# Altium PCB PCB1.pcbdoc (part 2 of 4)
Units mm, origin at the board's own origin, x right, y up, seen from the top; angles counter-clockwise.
Board outline 77.9 x 109.02 mm, 4 copper layers (Top Layer, Inner1, Inner2, Bottom Layer); 129 components, 135 nets, 715 pads, 425 vias.
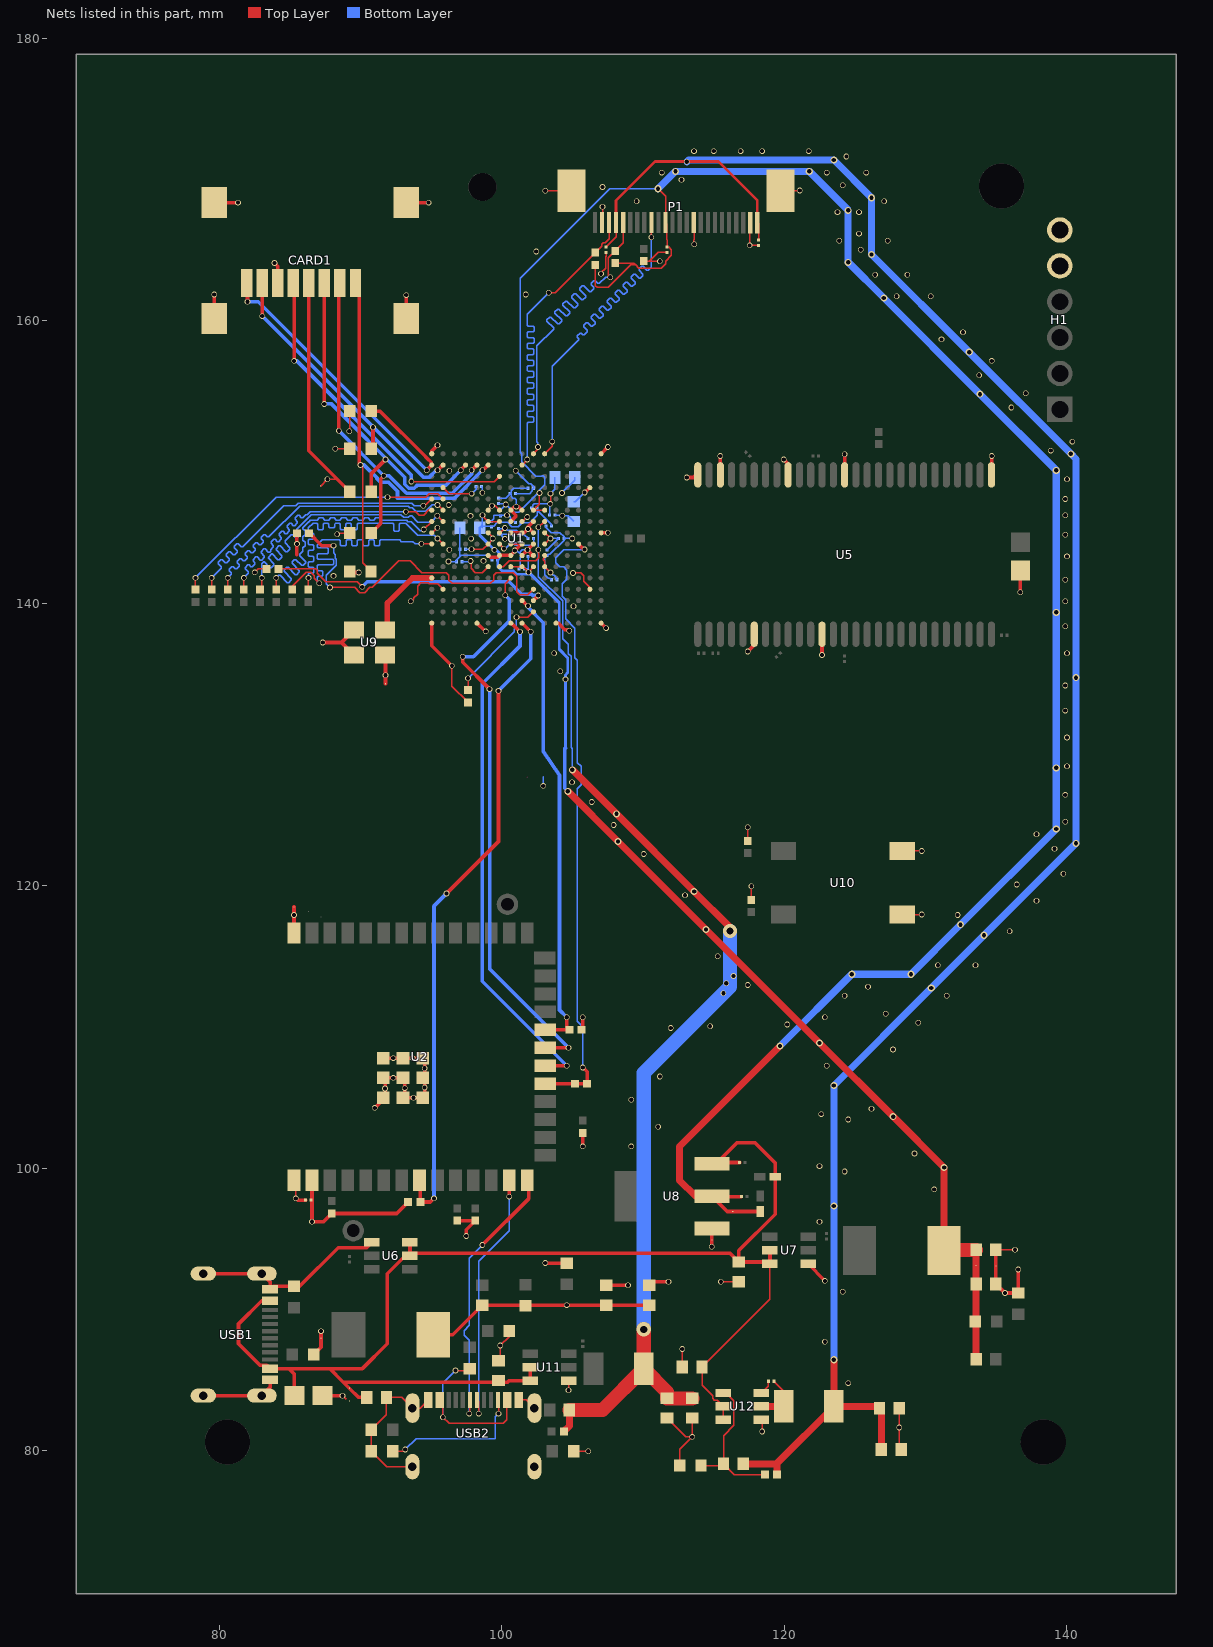
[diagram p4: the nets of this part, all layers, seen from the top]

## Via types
v1: diameter 0.4, hole 0.3, Top Layer to Bottom Layer, 387 vias
v2: diameter 0.5, hole 0.3, Top Layer to Bottom Layer, 36 vias
v3: diameter 1, hole 0.5, Top Layer to Bottom Layer, 2 vias

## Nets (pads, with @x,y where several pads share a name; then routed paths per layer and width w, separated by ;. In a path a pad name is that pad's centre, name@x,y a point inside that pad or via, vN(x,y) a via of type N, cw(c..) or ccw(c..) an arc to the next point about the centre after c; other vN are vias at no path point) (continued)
$1N63772: R42.1 USB2.B5 | length 10.5
  Top Layer w0.1: R42.1@92.252,79.942 93.023,79.942 v1(93.15,80.069) ; USB2.B5@99.726,83.574 99.754,83.546 v1(99.754,82.609)
  Bottom Layer w0.1: v1(93.15,80.069) 93.912,80.831 99.5,80.831 99.528,80.859 99.528,82.383 v1(99.754,82.609)
$1N63825: R44.2 USB2.A4B9 USB2.B4A9 | length 12.3
  Top Layer w0.1: USB2.A4B9@95.576,83.574 95.817,83.333 v1(95.817,82.355) 96.256,81.915 100.076,81.915 100.339,82.178 100.339,83.537 USB2.B4A9@100.376,83.574 ; v1(96.706,85.657) 97.586,85.657 R44.2@97.722,85.792
  Bottom Layer w0.1: v1(95.817,82.355) 95.817,84.768 v1(96.706,85.657)
$1N64401: C69.2 L4.1 U12.5 | length 3.6
  Top Layer w0.1: C69.2@119.253,84.895 119.95,84.198 L4.1@119.95,83.117
  Top Layer w0.5: U12.5@118.376,83.117 L4.1@119.95,83.117
$1N64402: C69.1 U12.6 | length 1
  Top Layer w0.1: U12.6@118.376,84.067 118.863,84.554 C69.1@118.863,84.895
$1N64403: C70.1 R46.2 R47.1 U12.1 | length 10.6
  Top Layer w0.1: R46.2@114.096,78.926 115.564,78.926 C70.1@115.691,79.053 ; U12.1@115.676,84.067 115.737,84.006 115.922,84.006 116.428,83.5 116.428,81.783 115.691,81.046 C70.1@115.691,79.053 ; R47.1@118.625,78.291 116.453,78.291 C70.1@115.691,79.053
$2N5507: R23.2 U1.P10 | length 20
  Top Layer w0.1: R23.2@84.185,142.426 86.8,142.426 86.906,142.32 86.906,142.132 87.522,141.516 89.742,141.516 v1(90.102,141.156)
  Top Layer w0.254: U1.P10@102.224,140.185 102.548,140.509 v1@102.548,140.521
  Bottom Layer w0.254: v1(90.102,141.156) 90.46,141.514 100.509,141.514 101.38,140.642 102.088,140.642 102.188,140.542 v1@102.569,140.542
  other v1: 102.569,140.542
$2N5509: R24.2 U1.N10 | length 23.9
  Top Layer w0.1: v1(87.816,141.114) 89.575,141.114 89.935,140.754 90.268,140.754 90.628,141.114 90.822,141.114 92.066,142.358 92.066,142.363 92.702,142.999 93.495,142.999 94.327,142.167 96.038,142.167 96.242,141.962 96.242,141.626 96.466,141.403 98.382,141.403 98.389,141.41 98.858,141.41 98.866,141.403 99.182,141.403 99.406,141.626 99.406,141.985 99.588,142.167 100.782,142.167 101.042,141.907 101.042,140.827 101.266,140.603 101.842,140.603 U1.N10@102.224,140.985
  Top Layer w0.254: R24.2@86.344,144.966 87.233,144.077 v1(88.07,144.077)
  Bottom Layer w0.1: v1(87.816,141.114) 87.562,141.368 87.562,141.992 88.27,142.7 88.27,143.125 88.197,143.198 88.197,143.442 88.07,143.569 v1(88.07,144.077)
$2N5511: R25.2 U1.R10 | length 7.9
  Top Layer w0.1: R25.2@97.595,133.842 v1(97.595,134.679) ; v1(101.024,138.997) 101.836,138.997 U1.R10@102.224,139.385
  Bottom Layer w0.1: v1(97.595,134.679) 100.876,137.96 100.876,138.147 101.024,138.295 v1(101.024,138.997)
+1V1: C25.2 C27.2 C28.2 C41.1 C42.1 C43.1 C44.1 C49.1 C53.1 C54.1 C61.1 L2.2 pad.55@104.453,129.091 pad.55@133.577,93.091 R15.2 U1.G6 U1.G7 U1.L8 U1.L9 U1.L10 | length 88.4
  Top Layer w0.1: v1@98.611,146.236 98.611,146.198 U1.G6@99.024,145.785 U1.G7@99.824,145.785 ; U1.L8@100.624,142.585 U1.L9@101.424,142.585 101.49,142.585 v1(101.882,142.193) 102.224,142.534 U1.L10@102.224,142.585
  Top Layer w0.5: v2(104.663,126.678) v2(108.218,123.123) v2(114.455,116.886) v2(122.493,108.847) v2(127.705,103.636) v2(131.313,100.028) L2.2@131.313,94.16 ; C25.2@133.577,86.458 C28.2@133.577,91.792 pad.55@133.577,93.091 C27.2@133.577,94.205
  Top Layer w1: L2.2@131.313,94.16 131.357,94.205 C27.2@133.577,94.205
  Bottom Layer w0.1: C61.1@98.485,145.41 98.619,145.544 v1(98.619,146.228) ; C61.1@98.549,145.347 98.652,145.45 99.401,145.45 99.673,145.723 100.394,145.723 100.701,145.416 101.145,145.416 101.434,145.707 101.952,145.707 102.489,146.243 102.489,146.49 ; C53.1@101.6,142.426 101.786,142.426 101.854,142.358 C49.1@101.854,143.315 ; C43.1@102.489,146.744 102.489,146.49 ; C44.1@103.505,145.474 103.505,145.584 102.599,146.49 102.489,146.49
  Bottom Layer w0.2: C61.1@98.422,145.347 98.422,144.814 v1(99.461,143.774) 99.589,143.774 99.683,143.68 99.683,143.677 99.789,143.571 99.789,143.155 C54.1@99.695,143.061 99.695,142.612 100.008,142.299 100.765,142.299 101.019,142.045 101.869,142.045 v1@101.882,142.058 ; v1(101.882,142.193) 101.892,142.193 104.052,140.033 104.052,137.287 104.06,137.279 104.06,136.905 104.052,136.897 104.052,136.735 104.651,136.136 104.651,135.071 104.499,134.919 v1(104.499,134.604) 104.499,129.729
  Bottom Layer w0.254: 104.499,129.729 104.453,129.729 pad.55@104.453,129.091 104.453,126.888 v2(104.663,126.678)
+1V8: C29.1 C32.2 C35.1 C62.1 C63.1 P1.11 pad.55@116.341,96.923 R38.2 R39.2 U1.F10 U1.F11 U8.2 | length 162.2
  Top Layer w0.1: v1(102.656,147.8) 102.656,147.557 102.642,147.543 102.642,147.227 102.656,147.212 102.656,147.017 U1.F10@102.224,146.585 U1.F11@103.024,146.585 ; R38.2@106.612,163.964 106.612,163.501 106.608,163.497 106.608,162.495 106.739,162.365 107.521,162.365 109.12,163.964 109.456,163.964 ; R39.2@108.009,164.091 109.329,164.091 109.456,163.964 ; v2(111.057,169.35) 111.581,168.825 P1.11@111.581,166.951 111.679,166.853 111.679,165.754 111.692,165.742 C35.1@111.692,165.227 ; 111.802,165.227 112.004,165.025 112.004,164.648 111.586,164.23 111.586,164.051 111.267,163.733 109.687,163.733 109.456,163.964
  Top Layer w0.254: C29.1@116.958,97.976 114.889,97.976 115.943,96.923 pad.55@116.341,96.923 C32.2@118.296,96.923
  Top Layer w0.5: U8.2@114.861,98.005 113.695,98.005 112.581,99.119 112.581,101.532 v2(119.693,108.644)
  Bottom Layer w0.1: C63.1@99.754,147.057 100.2,147.057 v1(100.271,146.985) ; C62.1@99.881,146.558 99.881,146.594 v1(100.271,146.985) ; v2(111.057,169.35) 107.628,169.35 101.278,163 101.278,150.681 101.384,150.575 101.384,150.006 102.396,148.994 102.827,148.994 102.863,149.03 102.929,149.03 103.044,148.915 103.044,148.388 102.656,148.001 v1(102.656,147.8) 102.544,147.8 101.181,146.437 100.848,146.437 100.3,146.985 v1(100.271,146.985)
  Bottom Layer w0.5: v2(111.057,169.35) v2(112.294,170.587) v2(121.758,170.587) v2(124.519,167.826) v2(124.519,164.143) v2(127.042,161.62) v2(133.861,154.801) v2(139.251,149.411) v2(139.251,139.352) v2(139.251,128.338) v2(139.251,124.011) v2(132.473,117.233) v2(128.964,113.724) v2(124.773,113.724) v2(119.693,108.644)
+2V5: C65.2 C67.2 C68.2 L3.2 R41.2 U1.G11 U1.L7 | length 84.7
  Top Layer w0.1: U1.L7@99.824,142.585 100.084,142.585 100.502,143.003 102.382,143.003 102.606,143.227 102.606,143.543 102.576,143.573 v1(102.576,143.785) ; v1(102.576,145.385) 102.976,145.785 U1.G11@103.024,145.785
  Top Layer w0.5: R41.2@104.378,81.339 104.772,81.733 C65.2@104.772,82.863 ; v2(104.982,128.202) v2(108.1,125.084) v2(113.609,119.574) 116.137,117.047 v3(116.137,116.772)
  Top Layer w1: C65.2@104.772,82.863 107.117,82.863 L3.2@110.038,85.784 ; v3(110.038,88.578) L3.2@110.038,85.784 ; C67.2@113.47,83.69 C68.2@111.692,83.69 111.692,84.13 L3.2@110.038,85.784
  Bottom Layer w0.1: v1(102.576,145.385) v1(102.576,143.785) 102.576,141.889 104.302,140.164 104.302,137.497 104.707,137.092 104.707,136.434 104.901,136.24 104.901,129.786 104.982,129.705 v2(104.982,128.202)
  Bottom Layer w1: v3(110.038,88.578) 110.038,106.736 v1(115.679,112.377) 116.137,112.835 v3(116.137,116.772)
  other v1: 115.883,113.089 116.391,113.597
+2V8: C34.1 C70.2 C72.2 C73.2 C74.1 L4.2 P1.4 P1.24 R47.2 | length 146.6
  Top Layer w0.1: C34.1@107.374,165.227 108.081,165.934 P1.4@108.081,166.951 ; P1.24@118.083,166.948 118.169,166.862 C74.1@118.169,165.735
  Top Layer w0.2: P1.4@108.081,166.951 108.081,168.526 110.831,171.276 115.33,171.276 118.083,168.523 P1.24@118.083,166.948
  Top Layer w0.5: C70.2@117.091,79.053 119.436,79.053 ; R47.2@119.491,78.291 119.491,78.998 119.436,79.053 ; L4.2@123.503,83.12 v2(123.503,86.419) ; C73.2@126.74,82.99 126.613,83.117 L4.2@123.5,83.117 119.436,79.053 ; C72.2@126.867,80.069 C73.2@126.867,82.863
  Bottom Layer w0.5: v1(113.089,171.255) 113.216,171.382 v2(123.503,171.382) v2(126.17,168.715) v2(126.17,164.695) v2(133.091,157.775) v2(140.284,150.581) 140.648,150.217 v2(140.648,134.724) v2(140.648,122.995) v2(134.135,116.482) v2(130.4,112.747) v2(123.503,105.85) v2(123.503,97.303) v2(123.503,86.419)
+3V3: C8.2 C17.2 C19.2 C22.2 C23.2 C37.1 C39.1 C40.1 C45.1 C46.1 C47.1 C48.1 C50.1 C51.1 C52.1 C55.1 C56.1 C57.1 C58.1 C59.1 CARD1.4 H1.5 L1.2 pad.55@87.15,148.289 R3.1 R4.1 R5.2 R7.2 R11.2 R16.2 R17.2 R18.2 R19.2 R20.2 R21.2 R22.2 R23.1 U1.F6 U1.F7 U1.G9 U1.H6 U1.H7 U1.H11 U1.J6 U1.J7 U1.J11 U1.K11 U1.L6 U1.L11 U2.2 U9.1 U9.4 | length 81.8
  Top Layer w0.1: v1(82.484,142.183) 82.727,142.426 R23.1@83.319,142.426 ; pad.55@87.15,148.289 v1(87.637,148.776) 88.328,148.776 88.33,148.778 ; v1(88.197,150.935) R18.2@89.221,150.935 ; v1(88.324,144.881) 88.409,144.966 R17.2@89.221,144.966 ; v1@89.221,152.205 R19.2@89.221,153.602 ; v1(97.776,142.985) 97.806,142.955 97.806,142.462 98.096,142.172 98.611,142.172 U1.L6@99.024,142.585 ; v1@97.849,143.823 98.045,143.823 98.065,143.803 98.642,143.803 U1.J6@99.024,144.185 99.352,144.513 v1(99.352,144.584) 99.352,144.657 U1.H6@99.024,144.985 ; U1.F6@99.024,146.585 99.292,146.853 v1(99.292,146.902) 99.506,146.902 U1.F7@99.824,146.585 ; U1.J7@99.824,144.185 100.135,143.874 v1@100.135,143.823 ; U1.H7@99.824,144.985 99.871,144.985 v1(100.207,145.321) ; U1.G9@101.424,145.785 101.748,146.109 v1(101.786,146.109) ; U1.K11@103.024,143.385 103.024,143.258 102.929,143.163 102.929,143.061 103.024,142.966 U1.L11@103.024,142.585 v1(103.437,142.172) ; U1.J11@103.024,144.185 103.424,144.585 v1(103.437,144.585) 103.037,144.985 U1.H11@103.024,144.985
  Top Layer w0.254: CARD1.4@86.319,162.67 86.319,150.789 88.33,148.778 R20.2@89.221,147.887 ; U2.2@86.668,99.132 86.546,99.01 v1(86.546,96.198) 87.36,96.198 R7.2@87.943,96.781 92.538,96.781 R5.2@93.352,97.595 ; v1(87.308,137.219) 88.635,137.219 ; R16.2@89.217,142.247 89.293,142.172 v1(89.848,142.172) ; U9.1@89.51,136.344 88.635,137.219 ; U9.4@89.51,138.094 88.635,137.219 ; L1.2@95.134,88.197 96.517,88.197 C19.2@98.611,90.291 101.605,90.291 R11.2@101.659,90.237 101.712,90.291 v1(104.594,90.291) C23.2@107.374,90.291 C22.2@110.422,90.291 ; R21.2@96.833,96.273 R22.2@98.103,96.273 97.468,95.638 v1(97.468,95.182) ; R3.1@105.648,109.787 105.723,109.862 v1(105.723,110.676) ; v1(105.723,101.532) R4.1@105.723,102.496 ; v1(136.711,140.775) C8.2@136.711,142.315
  Bottom Layer w0.1: C51.1@97.155,142.934 97.725,142.934 v1(97.776,142.985) ; C56.1@97.409,143.823 97.833,143.823 v1(97.841,143.815) ; C37.1@98.552,148.268 98.611,148.209 v1(98.611,147.819) ; C45.1@99.754,145.288 100.174,145.288 v1(100.207,145.321) 100.377,145.151 101.017,145.151 101.136,145.032 101.136,144.922 C46.1@101.219,144.839 101.591,144.839 C47.1@101.845,144.585 ; v1(100.135,143.864) 100.235,143.864 C57.1@100.575,144.204 ; C50.1@100.965,147.76 101.964,147.76 102.152,147.947 102.152,148.058 C39.1@102.235,148.141 102.235,148.251 102.033,148.453 101.908,148.453 v1(100.976,149.385) ; C52.1@103.183,143.764 C55.1@104.004,144.585 v1(103.437,144.585) ; v1(103.437,142.172) 103.633,141.976 103.684,141.976 103.886,141.774 C48.1@103.886,141.664 ; C40.1@103.759,146.236 104.22,146.236 v1(104.27,146.186) 104.692,146.186 C59.1@105.088,145.79 ; v1(104.248,147.808) 105.153,148.712 C58.1@105.153,148.903
  other v1: 88.07,141.932 89.188,152.171
+5V: C20.2 C26.2 C30.1 C31.2 C33.2 C66.2 C71.2 pad.55@89.194,84.406 U6.2 U6.3 U7.2 U7.3 U8.3 U11.2 U11.3 U12.2 U12.3 USB1.A4B9 USB1.B4A9 | length 100.1
  Top Layer w0.1: U12.3@115.676,82.167 U12.2@115.676,83.117 115.228,83.565 115.042,83.565 114.924,83.683 114.924,83.869 114.17,84.623 C71.2@114.17,85.911 118.978,90.719 U7.3@118.978,93.216
  Top Layer w0.254: USB1.A4B9@83.574,90.597 82.977,90.597 81.339,88.959 81.339,87.563 82.884,86.018 83.353,86.018 USB1.B4A9@83.574,85.797 84.904,85.797 ; C33.2@85.292,83.879 85.292,85.409 84.904,85.797 ; C20.2@90.418,83.752 89.848,83.752 pad.55@89.194,84.406 88.767,84.833 ; U6.3@93.484,94.735 U6.2@93.484,93.785 ; U11.2@102.013,85.883 U11.3@102.013,84.933 100.489,84.933 100.389,84.833 88.767,84.833 ; U8.3@114.861,100.305 115.164,100.305 U8.3@115.248,100.389 ; C30.1@116.831,100.389 U8.3@115.248,100.389 ; U7.2@118.978,94.166 U7.3@118.978,93.216 118.852,93.342 C26.2@116.772,93.342 ; 84.904,85.797 87.803,85.797 ; 87.803,85.797 90.115,85.797 91.88,87.562 91.88,92.515 93.15,93.785 U6.2@93.484,93.785 ; 87.803,85.797 88.767,84.833 ; U6.2@93.484,93.785 93.649,93.95 116.163,93.95 C26.2@116.772,93.342 ; U8.3@115.248,100.389 116.645,101.786 117.915,101.786 119.349,100.352 C31.2@119.349,99.373 119.349,96.731 116.772,94.154 C26.2@116.772,93.342
CCLK: R6.1 R6.2 U1.J14 U2.19 | length 44.6
  Top Layer w0.254: U2.19@103.188,105.977 R6.1@105.163,105.977 R6.2@106.029,105.977 106.029,106.814 v1(105.723,107.12) ; U1.J14@105.424,144.185 105.807,143.802 v1(105.85,143.802)
  Bottom Layer w0.1: v1(105.723,107.12) 105.723,109.998 105.321,110.4 105.321,126.873 105.596,127.148 105.596,128.456 105.342,128.71 105.321,128.71 105.321,135.97 105.169,136.122 105.169,138.224 104.51,138.882 104.51,140.247 104.282,140.475 104.282,141.366 104.601,141.685 104.601,142.338 104.365,142.574 104.08,142.574 103.795,142.858 103.795,143.226 104.371,143.802 v1(105.85,143.802)
CRYSTAL: U1.M1 U9.3 | length 5.9
  Top Layer w0.4: U9.3@91.71,138.094 91.88,138.264 91.88,140.013 93.652,141.785 U1.M1@95.024,141.785
D0: R26.1 U1.E2 | length 21
  Top Layer w0.1: R26.1@78.291,140.954 v1(78.291,141.791) ; v1@91.88,147.506 94.604,147.506 94.866,147.767 95.442,147.767 U1.E2@95.824,147.385
  Bottom Layer w0.1: v1(78.291,141.791) 84.006,147.506 v1(91.889,147.506)
D1: R27.1 U1.E1 | length 21.1
  Top Layer w0.1: R27.1@79.434,140.954 v1(79.434,141.791) ; v1(94.42,146.9) 94.539,146.9 U1.E1@95.024,147.385
  Bottom Layer w0.1: v1(79.434,141.791) 80.119,142.476 80.119,142.576 79.901,142.793 79.901,142.893 80.084,143.076 80.184,143.076 80.402,142.859 80.502,142.859 80.685,143.042 80.685,143.142 80.467,143.359 80.467,143.459 80.65,143.642 80.75,143.642 80.967,143.424 81.067,143.424 81.25,143.607 81.25,143.707 81.033,143.925 81.033,144.025 81.216,144.208 81.316,144.208 81.533,143.99 81.633,143.99 84.543,146.9 85.403,146.9 85.581,147.078 93.613,147.078 93.791,146.9 v1(94.42,146.9)
D2: R28.1 U1.F2 | length 21.5
  Top Layer w0.1: R28.1@80.577,140.954 v1(80.577,141.791) ; v1(95.433,146.955) 95.454,146.955 U1.F2@95.824,146.585
  Bottom Layer w0.1: v1(80.577,141.791) 80.831,142.045 80.831,142.145 80.677,142.299 80.677,142.399 80.86,142.582 80.96,142.582 81.114,142.428 81.214,142.428 81.396,142.61 81.396,142.71 81.242,142.864 81.242,142.964 81.425,143.147 81.525,143.147 81.679,142.993 81.779,142.993 81.962,143.176 81.962,143.276 81.808,143.43 81.808,143.53 81.991,143.713 82.091,143.713 82.245,143.559 82.345,143.559 82.528,143.742 82.528,143.842 82.374,143.996 82.374,144.096 82.557,144.279 82.657,144.279 82.811,144.125 82.911,144.125 83.094,144.308 83.094,144.408 82.94,144.562 82.94,144.662 83.122,144.844 83.222,144.844 83.376,144.69 83.476,144.69 85.664,146.878 93.361,146.878 93.471,146.768 93.639,146.768 93.91,146.498 94.586,146.498 95.043,146.955 v1(95.433,146.955)
D3: R29.1 U1.F1 | length 20.7
  Top Layer w0.1: R29.1@81.72,140.954 v1(81.72,141.791) ; v1(93.195,146.476) 93.894,146.476 94.126,146.244 94.459,146.244 94.817,146.602 95.007,146.602 U1.F1@95.024,146.585
  Bottom Layer w0.1: v1(81.72,141.791) 82.039,142.11 82.039,142.21 81.822,142.428 81.822,142.528 82.004,142.71 82.104,142.71 82.224,142.591 82.324,142.591 82.507,142.774 82.507,142.874 82.387,142.993 82.387,143.093 82.57,143.276 82.67,143.276 82.888,143.059 82.988,143.059 83.17,143.241 83.17,143.341 82.953,143.559 82.953,143.659 83.136,143.842 83.236,143.842 83.453,143.624 83.553,143.624 83.606,143.677 83.606,143.773 83.818,143.985 83.818,144.085 83.649,144.255 83.649,144.355 83.831,144.537 83.931,144.537 84.101,144.368 84.201,144.368 84.384,144.551 84.384,144.651 84.214,144.82 84.214,144.92 84.397,145.103 84.497,145.103 84.666,144.934 84.766,144.934 84.949,145.117 84.949,145.217 84.78,145.386 84.78,145.486 84.963,145.669 85.063,145.669 85.232,145.5 85.332,145.5 85.515,145.682 85.515,145.782 85.346,145.952 85.346,146.052 85.529,146.235 85.629,146.235 85.798,146.065 85.898,146.065 86.106,146.274 86.203,146.274 86.405,146.476 v1(93.195,146.476)
D4: R30.1 U1.G2 | length 21.3
  Top Layer w0.1: R30.1@82.863,140.954 82.99,141.081 v1(82.99,141.791) ; v1(95.418,146.188) 95.421,146.188 U1.G2@95.824,145.785
  Bottom Layer w0.1: v1(82.99,141.791) 82.99,142.778 83.136,142.924 83.154,142.924 83.566,142.512 83.666,142.512 83.849,142.695 83.849,142.795 83.437,143.207 83.437,143.225 83.702,143.49 83.72,143.49 84.132,143.078 84.232,143.078 84.414,143.261 84.414,143.361 84.003,143.773 84.003,143.873 84.185,144.056 84.285,144.056 84.697,143.644 84.797,143.644 84.98,143.827 84.98,143.927 84.641,144.266 84.641,144.429 85.066,144.855 85.166,144.855 85.385,144.636 85.485,144.636 85.668,144.819 85.668,144.919 85.449,145.137 85.449,145.237 86.488,146.276 92.826,146.276 93.028,146.074 93.361,146.074 93.488,146.201 93.597,146.201 94.049,145.749 94.978,145.749 v1(95.418,146.188)
D5: R31.1 U1.G1 | length 21
  Top Layer w0.1: R31.1@84.006,140.954 v1(84.006,141.791) ; v1(94.453,145.22) 94.459,145.22 U1.G1@95.024,145.785
  Bottom Layer w0.1: v1(84.006,141.791) 84.185,141.97 84.285,141.97 84.794,141.461 84.894,141.461 85.077,141.643 85.077,141.743 84.567,142.252 84.567,142.352 84.75,142.535 84.85,142.535 85.359,142.026 85.459,142.026 85.642,142.209 85.642,142.309 85.133,142.818 85.133,142.918 85.297,143.082 85.397,143.082 85.809,142.669 85.909,142.669 86.092,142.852 86.092,142.952 85.68,143.365 85.68,143.465 85.88,143.665 85.88,143.923 85.951,143.993 85.992,143.993 86.063,144.064 86.063,144.323 85.992,144.393 85.951,144.393 85.88,144.464 85.88,144.723 85.951,144.793 85.992,144.793 86.063,144.864 86.063,145.123 85.992,145.193 85.951,145.193 85.88,145.264 85.88,145.337 86.326,145.784 86.348,145.784 86.438,145.874 86.923,145.874 86.994,145.945 86.994,145.976 87.065,146.047 87.323,146.047 87.394,145.976 87.394,145.945 87.465,145.874 87.723,145.874 87.794,145.945 87.794,145.976 87.865,146.047 88.123,146.047 88.194,145.976 88.194,145.945 88.265,145.874 88.523,145.874 88.594,145.945 88.594,145.976 88.665,146.047 88.923,146.047 88.994,145.976 88.994,145.945 89.065,145.874 89.323,145.874 89.394,145.945 89.394,145.976 89.465,146.047 89.723,146.047 89.794,145.976 89.794,145.945 89.865,145.874 90.123,145.874 90.194,145.945 90.194,145.976 90.265,146.047 90.523,146.047 90.594,145.976 90.594,145.945 90.665,145.874 90.923,145.874 90.994,145.945 90.994,145.976 91.065,146.047 91.323,146.047 91.394,145.976 91.394,145.945 91.465,145.874 93.249,145.874 93.339,145.784 93.568,145.784 94.222,145.13 94.363,145.13 v1(94.453,145.22)
D6: R32.1 U1.J1 | length 20.9
  Top Layer w0.1: R32.1@85.149,140.954 85.149,141.216 86.125,142.193 86.458,142.193 86.694,141.957 86.694,141.77 v1(87.054,141.41) ; v1(94.293,144.204) 95.005,144.204 U1.J1@95.024,144.185
  Bottom Layer w0.1: v1(87.054,141.41) 86.906,141.558 86.906,141.842 86.977,141.913 87.241,141.913 87.312,141.983 87.312,142.242 87.241,142.313 86.977,142.313 86.906,142.383 86.906,142.642 86.977,142.713 87.999,142.713 88.07,142.783 88.07,143.042 87.999,143.113 86.977,143.113 86.906,143.183 86.906,143.442 86.977,143.513 87.618,143.513 87.689,143.583 87.689,143.842 87.618,143.913 86.977,143.913 86.906,143.983 86.906,144.116 87.268,144.479 88.486,144.479 88.556,144.408 88.556,144.148 88.627,144.077 88.886,144.077 88.956,144.148 88.956,144.408 89.027,144.479 89.286,144.479 89.356,144.408 89.356,144.148 89.427,144.077 89.686,144.077 89.756,144.148 89.756,144.408 89.827,144.479 90.086,144.479 90.156,144.408 90.156,144.148 90.227,144.077 90.486,144.077 90.556,144.148 90.556,144.408 90.627,144.479 90.886,144.479 90.956,144.408 90.956,144.148 91.027,144.077 91.286,144.077 91.356,144.148 91.356,144.408 91.427,144.479 92.748,144.479 92.875,144.352 93.697,144.352 93.845,144.204 v1(94.293,144.204)
D7: R34.1 U1.J2 | length 21
  Top Layer w0.1: R34.1@86.292,140.954 v1(86.292,141.791) ; v1(95.436,144.585) 95.436,144.573 U1.J2@95.824,144.185
  Bottom Layer w0.1: v1(86.292,141.791) 86.292,142.065 86.363,142.136 86.606,142.136 86.677,142.206 86.677,142.465 86.606,142.536 86.363,142.536 86.292,142.606 86.292,142.865 86.363,142.936 86.606,142.936 86.677,143.006 86.677,143.265 86.606,143.336 86.363,143.336 86.292,143.406 86.292,143.665 86.363,143.736 86.606,143.736 86.677,143.806 86.677,144.065 86.606,144.136 86.363,144.136 86.292,144.206 86.292,144.465 86.363,144.536 86.606,144.536 86.677,144.606 86.677,144.865 86.606,144.936 86.363,144.936 86.292,145.006 86.292,145.347 86.619,145.674 86.867,145.674 86.938,145.603 86.938,145.265 87.009,145.194 87.267,145.194 87.338,145.265 87.338,145.603 87.409,145.674 87.667,145.674 87.738,145.603 87.738,145.406 87.809,145.336 88.067,145.336 88.138,145.406 88.138,145.603 88.209,145.674 88.467,145.674 88.538,145.603 88.538,145.265 88.609,145.194 88.867,145.194 88.938,145.265 88.938,145.603 89.009,145.674 89.267,145.674 89.338,145.603 89.338,145.265 89.409,145.194 89.667,145.194 89.738,145.265 89.738,145.603 89.809,145.674 92.262,145.674 92.333,145.603 92.333,145.164 92.404,145.093 92.662,145.093 92.733,145.164 92.733,145.603 92.804,145.674 93.166,145.674 94.022,144.818 95.203,144.818 v1(95.436,144.585)
DIN: U1.T8 U2.20 | length 36.6
  Top Layer w0.254: U1.T8@100.624,138.585 100.674,138.585 v1(101.278,137.981) ; U2.20@103.188,107.247 v1(104.58,107.247)
  Bottom Layer w0.254: v1(101.278,137.981) 101.278,136.965 98.611,134.298 98.611,113.216 v1(104.58,107.247)
DN: U2.13 USB2.A7 | length 18.5
  Top Layer w0.1: USB2.A7@98.226,83.574 98.357,83.443 v1(98.357,82.609)
  Top Layer w0.254: v1(100.516,97.976) 100.516,99.01 U2.13@100.638,99.132
  Bottom Layer w0.1: v1(98.357,82.609) 98.357,93.404 100.516,95.563 v1(100.516,97.976)
DONE: pad.55@103.564,128.456 R3.2 U1.P9 U2.22 | length 33.3
  Top Layer w0.254: U1.P9@101.424,140.185 101.794,139.815 v1(101.842,139.815) ; U2.22@103.188,109.787 R3.2@104.782,109.787 104.58,109.989 v1(104.58,110.676)
  Bottom Layer w0.254: v1(101.842,139.815) 101.842,139.703 102.929,138.616 102.929,129.472 104.072,127.821 104.072,111.184 v1(104.58,110.676)
DOUT: U1.M8 U2.21 | length 40
  Top Layer w0.1: v1(100.224,140.57) 100.224,141.385 U1.M8@100.624,141.785
  Top Layer w0.254: v1(97.214,136.203) 97.214,135.822 v1(99.119,133.917) ; U2.21@103.188,108.517 v1(104.707,108.517)
  Bottom Layer w0.254: v1(97.214,136.203) 97.976,136.203 100.508,138.735 100.508,140.286 v1(100.224,140.57) ; v1(99.119,133.917) 99.119,114.105 v1(104.707,108.517)
DP: U2.14 USB2.A6 | length 19.5
  Top Layer w0.1: v1@97.726,82.609 USB2.A6@97.726,83.574
  Top Layer w0.254: v1(98.611,94.547) 101.908,97.844 U2.14@101.908,99.132
  Bottom Layer w0.1: v1(97.678,82.609) 97.678,87.799 97.32,88.157 97.32,88.49 97.678,88.848 97.678,93.614 v1(98.611,94.547)
FSCL: P1.5 R39.1 U1.A10 | length 27
  Top Layer w0.1: U1.A10@102.224,150.585 102.548,150.909 v1(102.548,151.062) ; v1(107.671,163.084) 107.537,163.218 107.537,164.457 108.009,164.929 R39.1@108.009,164.957 108.581,165.529 P1.5@108.581,166.951
  Bottom Layer w0.1: v1(102.548,151.062) 102.548,151.347 102.467,151.428 102.467,158.219 103.656,159.408 103.656,159.508 103.184,159.98 103.184,160.08 103.367,160.263 103.467,160.263 103.939,159.791 104.039,159.791 104.222,159.974 104.222,160.074 103.75,160.546 103.75,160.646 103.933,160.829 104.033,160.829 104.505,160.356 104.605,160.356 104.788,160.539 104.788,160.639 104.315,161.111 104.315,161.211 104.498,161.394 104.598,161.394 105.07,160.922 105.17,160.922 105.353,161.105 105.353,161.205 104.931,161.627 104.931,161.727 105.114,161.91 105.214,161.91 105.636,161.488 105.736,161.488 105.919,161.671 105.919,161.771 105.497,162.193 105.497,162.293 105.68,162.476 105.78,162.476 106.202,162.054 106.302,162.054 106.508,162.259 106.508,162.359 106.318,162.549 106.318,162.649 106.5,162.832 106.6,162.832 106.79,162.642 106.89,162.642 107.332,163.084 v1(107.671,163.084)
FSDA: P1.3 R38.1 U1.B9 | length 27
  Top Layer w0.1: U1.B9@101.424,149.785 101.786,150.147 v1(101.786,150.173) ; v1(103.31,161.984) 103.766,161.984 R38.1@106.612,164.83 107.062,165.28 107.062,165.416 107.18,165.534 107.316,165.534 107.581,165.799 P1.3@107.581,166.951
  Bottom Layer w0.1: v1(101.786,150.173) 101.786,152.727 101.857,152.798 102.173,152.798 102.244,152.869 102.244,153.127 102.173,153.198 101.857,153.198 101.786,153.269 101.786,153.538 101.857,153.608 102.173,153.608 102.244,153.679 102.244,153.938 102.173,154.008 101.857,154.008 101.786,154.079 101.786,154.338 101.857,154.408 102.173,154.408 102.244,154.479 102.244,154.738 102.173,154.808 101.857,154.808 101.786,154.879 101.786,155.138 101.857,155.208 102.173,155.208 102.244,155.279 102.244,155.538 102.173,155.608 101.857,155.608 101.786,155.679 101.786,155.938 101.857,156.008 102.173,156.008 102.244,156.079 102.244,156.338 102.173,156.408 101.857,156.408 101.786,156.479 101.786,156.738 101.857,156.808 102.173,156.808 102.244,156.879 102.244,157.138 102.173,157.208 101.857,157.208 101.786,157.279 101.786,157.538 101.857,157.608 102.173,157.608 102.244,157.679 102.244,157.938 102.173,158.008 101.857,158.008 101.786,158.079 101.786,158.338 101.857,158.408 102.223,158.408 102.294,158.479 102.294,158.738 102.223,158.808 101.857,158.808 101.786,158.879 101.786,159.138 101.857,159.208 102.223,159.208 102.294,159.279 102.294,159.538 102.223,159.608 101.857,159.608 101.786,159.679 101.786,160.46 v1(103.31,161.984)
GND: C17.1 C20.1 C22.1 C23.1 C26.1 C27.1 C28.1 C33.1 C34.2 C35.2 C37.2 C39.2 C40.2 C41.2 C42.2 C43.2 C44.2 C45.2 C46.2 C47.2 C48.2 C49.2 C50.2 C51.2 C52.2 C53.2 C54.2 C55.2 C56.2 C57.2 C58.2 C59.2 C61.2 C62.2 C63.2 C66.1 C67.1 C68.1 C71.1 C72.1 C73.1 C74.2 CARD1.6 CARD1.9 CARD1.10 CARD1.11 CARD1.12 H1.6 P1.2 P1.15 P1.23 P1.25 P1.26 pad.55@85.271,118.491 pad.55@87.181,87.943 pad.55@89.213,83.498 pad.55@91.753,134.298 pad.55@102.929,127.694 pad.55@114.861,94.892 pad.55@134.977,93.052 R9.1 R10.1 R12.1 R14.1 R24.1 R25.1 R35.2 R36.2 R37.2 R40.1 R42.2 R43.2 R45.1 R46.1 U1.A1 U1.A16 U1.D2 U1.D15 U1.F8 U1.F9 U1.G8 U1.G10 U1.H1 U1.H8 U1.H9 U1.H10 U1.H16 U1.J8 U1.J9 U1.J10 U1.K6 U1.K7 U1.K8 U1.K9 U1.K10 U1.N2 U1.N15 U1.T1 U1.T5 U1.T12 U1.T16 U2.1 U2.40 U2.41 U5.6 U5.12 U5.28 U5.41 U5.46 U5.52 U5.54 U6.4 U7.4 U8.1 U9.2 U10.2 U10.4 U11.4 U12.4 USB1.1 USB1.2 USB1.3 USB1.4 USB1.A1B12 USB1.B1A12 USB2.1 USB2.2 USB2.3 USB2.4 USB2.A1B12 USB2.B1A12 | length 181.8
  Top Layer w0.1: U2.1@85.271,99.132 85.398,99.005 v1(85.398,97.849) ; v1(88.705,83.879) 88.959,83.625 ; v1(93.531,140.14) 93.604,140.14 93.764,140.299 93.764,140.383 94.018,140.637 94.018,141.195 94.253,141.431 94.78,141.431 94.838,141.373 95.436,141.373 U1.N2@95.824,140.985 ; USB2.3@93.656,78.849 91.838,78.849 R42.2@90.745,79.942 R43.2@90.745,81.466 91.818,82.538 C20.1@91.818,83.752 92.903,83.752 USB2.1@93.656,82.999 94.201,82.999 USB2.A1B12@94.776,83.574 ; 95.182,145.093 95.424,145.335 v1(95.424,145.347) ; U1.D2@95.824,148.185 96.249,147.76 96.458,147.76 96.466,147.767 97.582,147.767 97.589,147.76 v1@97.849,147.76 ; v1(96.452,135.568) 96.452,134.119 R25.1@97.595,132.976 ; C66.1@99.754,86.357 99.881,86.484 v1(99.881,87.435) 100.507,88.061 R45.1@100.507,88.451 ; U1.J8@100.624,144.185 U1.J9@101.367,144.185 ; USB2.B1A12@101.176,83.574 101.721,83.574 USB2.2@102.296,82.999 ; v1(103.056,169.205) P1.26@104.926,169.205 ; v1(103.424,147.033) 103.437,147.046 v1(103.437,147.76) ; v1(104.707,84.26) 104.713,84.266 U11.4@104.713,84.933 ; v1(105.024,142.137) 105.163,142.137 105.193,142.167 105.582,142.167 105.806,141.943 105.806,141.553 106.224,141.136 U1.N15@106.224,140.985 ; R40.1@105.079,79.942 v1(106.104,79.942) ; v1(107.01,163.33) 107.01,163.398 107.337,163.725 107.337,164.54 107.374,164.577 C34.2@107.374,164.837 ; P1.2@107.081,166.951 107.12,166.99 v1(107.12,168.08) ; R35.2@110.041,164.218 110.438,164.218 ; v1(111.184,164.218) 110.438,164.218 ; C68.1@111.692,82.29 113.024,80.958 v1(113.47,80.958) ; C35.2@111.692,164.837 111.057,164.837 110.438,164.218 ; R46.1@112.589,78.926 112.589,80.077 v1(113.47,80.958) ; C71.1@112.77,85.911 v1(112.77,87.181) ; C67.1@113.47,82.29 v1(113.47,80.958) ; P1.15@113.577,166.95 113.614,166.913 113.614,165.751 113.597,165.733 v1@113.597,165.413 ; v1(115.502,91.942) C26.1@116.772,91.942 ; R36.2@117.407,123.174 v1(117.407,124.138) ; P1.23@117.583,166.948 117.534,166.899 v1(117.534,165.341) 117.538,165.345 C74.2@118.169,165.345 ; R37.2@117.661,118.983 v1(117.661,119.947) ; U12.4@118.376,82.167 118.423,82.12 v1(118.423,81.339) ; P1.25@119.728,169.212 121.079,169.212 v1(121.09,169.223) ; C73.1@128.14,82.99 v1(128.14,81.618) 128.14,80.196 C72.1@128.267,80.069 ; U10.4@128.338,117.951 v1(129.726,117.951) ; U10.2@128.338,122.451 v1(129.726,122.451) ; C27.1@134.977,94.205 v1(136.33,94.205)
  Top Layer w0.254: USB1.4@78.849,83.877 USB1.2@82.999,83.877 83.574,84.452 USB1.B1A12@83.574,84.997 ; USB1.3@78.849,92.517 USB1.1@82.999,92.517 83.574,91.942 USB1.A1B12@83.574,91.397 83.794,91.617 R9.1@85.276,91.617 85.657,91.617 88.393,94.354 90.108,94.354 90.118,94.364 90.413,94.364 U6.4@90.784,94.735 ; CARD1.10@79.619,160.17 v1(79.619,161.861) ; CARD1.9@79.619,168.37 v1(81.304,168.37) ; v1(83.891,164.097) 84.119,163.87 CARD1.6@84.119,162.67 ; pad.55@85.271,118.491 v1(85.271,117.919) 85.271,116.759 U2.40@85.398,116.632 ; v1(85.398,97.849) 85.525,97.722 C17.1@86.097,97.722 ; 85.478,143.442 v1(85.478,144.197) R24.1@85.478,144.966 ; R10.1@86.664,86.8 87.181,87.316 pad.55@87.181,87.943 v1(87.181,88.451) ; C33.1@87.292,83.879 v1(88.705,83.879) ; v1(90.992,104.255) 91.718,104.982 v1(91.718,105.635) 91.718,106.382 v1(92.294,106.382) 93.118,106.382 v1(93.118,105.66) 93.118,104.982 v1(93.738,104.982) 94.518,104.982 v1(94.518,105.703) v1(94.518,107.066) 94.518,107.782 v1(93.669,107.782) U2.41@92.991,107.782 v1(92.294,107.782) U2.41@91.718,107.782 ; U9.2@91.71,136.344 91.753,136.301 v1(91.753,134.903) pad.55@91.753,134.298 ; CARD1.11@93.219,160.17 v1(93.219,161.819) ; CARD1.12@93.219,168.37 v1(94.801,168.37) ; U1.T1@95.024,138.585 95.024,136.996 v1(96.452,135.568) ; U1.A1@95.024,150.585 95.024,150.777 v1(95.436,151.189) ; U1.T5@98.224,138.585 98.807,138.002 v1(98.844,138.002) ; U1.K6@99.024,143.385 99.165,143.244 99.683,143.244 U1.K7@99.824,143.385 U1.K8@100.624,143.385 100.91,143.672 v1(100.91,143.728) 101.367,144.185 U1.J9@101.424,144.185 ; U1.H8@100.624,144.985 U1.H9@101.424,144.985 101.574,144.985 v1(101.843,145.253) ; U1.G8@100.624,145.785 100.976,146.137 100.976,146.233 U1.F8@100.624,146.585 100.878,146.839 v1(101.014,146.839) 101.17,146.839 U1.F9@101.424,146.585 ; U1.K9@101.424,143.385 101.802,143.764 v1(101.802,143.777) ; U1.K10@102.068,143.413 102.068,143.511 v1(101.802,143.777) ; U1.J10@102.224,144.185 102.21,144.185 v1(101.802,143.777) ; U1.H10@102.224,144.985 101.955,145.253 v1(101.843,145.253) ; U1.G10@102.224,145.785 101.843,145.404 v1(101.843,145.253) ; v1(103.056,93.268) R12.1@104.58,93.268 ; U1.T12@103.824,138.585 104.011,138.585 104.165,138.431 104.165,138.395 104.434,138.126 104.694,138.126 v1(104.767,138.053) ; v1@105.85,147.887 105.926,147.887 U1.D15@106.224,148.185 ; U1.T16@107.024,138.585 v1(107.374,138.235) ; U1.H16@107.024,144.985 v1(107.501,144.987) ; U1.A16@107.024,150.585 v1(107.501,151.062) ; C23.1@107.374,91.691 v1(108.928,91.691) ; C22.1@110.422,91.691 110.673,91.942 v1(111.793,91.942) ; v1(113.089,148.903) 113.557,148.903 U5.54@113.865,149.211 ; v1(114.861,94.429) pad.55@114.861,94.892 U8.1@114.861,95.705 ; U5.52@115.465,149.211 v1(115.465,150.427) ; v1(117.407,136.584) 117.865,137.042 U5.6@117.865,137.8 ; v1(119.947,150.173) 120.265,149.855 U5.46@120.265,149.084 ; U7.4@121.678,93.216 122.868,92.026 v1(122.868,92.007) ; v1(122.665,136.33) U5.12@122.665,137.8 ; U5.41@124.265,149.211 v1(124.265,150.554) ; U5.28@134.665,149.084 134.679,149.098 v1(134.679,150.427) ; C27.1@134.977,94.205 pad.55@134.977,93.052 C28.1@134.977,91.792 v1(135.621,91.148) R14.1@136.563,91.148 v1(136.563,92.808)
  Bottom Layer w0.1: v1@96.198,142.934 C51.2@96.765,142.934 96.765,143.044 97.019,143.298 ; C61.2@97.022,145.347 97.022,143.826 C56.2@97.019,143.823 97.019,143.298 ; v1(97.848,147.761) 98.162,148.075 C37.2@98.162,148.268 ; C41.2@99.246,145.796 99.424,145.974 99.424,146.232 99.816,146.232 C62.2@99.881,146.168 99.945,146.232 v1(100.351,146.232) 100.451,146.232 100.574,146.11 100.574,146.05 100.809,145.814 100.869,145.814 C42.2@100.956,145.728 ; C54.2@99.305,143.061 98.979,143.387 97.107,143.387 97.019,143.298 ; C45.2@99.754,144.898 C45.2@99.863,144.898 ; C63.2@99.754,147.447 100.262,147.447 C50.2@100.575,147.76 ; v1(100.21,144.551) C45.2@99.863,144.898 ; v1(100.91,143.728) 101.05,143.728 101.293,143.486 ; v1(101.014,146.839) 101.014,147.32 100.887,147.448 100.776,147.448 100.658,147.566 100.658,147.677 C50.2@100.575,147.76 ; C53.2@101.21,142.426 101.293,142.509 101.293,143.215 101.393,143.315 C49.2@101.464,143.315 101.293,143.486 ; C39.2@101.845,148.141 100.845,148.141 100.658,147.953 100.658,147.843 C50.2@100.575,147.76 ; C43.2@102.099,146.744 102.182,146.827 102.182,146.937 102.3,147.056 102.678,147.056 102.701,147.033 v1(103.424,147.033) 103.369,146.977 C40.2@103.369,146.236 ; C47.2@102.235,144.585 102.235,144.209 102.135,144.109 ; v1(102.929,127.059) pad.55@102.929,127.694 ; C44.2@103.115,145.474 103.115,145.363 103.481,144.997 104.092,144.997 104.394,144.695 C55.2@104.394,144.585 ; v1(103.437,147.76) 103.753,148.076 C58.2@103.753,148.903 ; C48.2@103.496,141.664 103.39,141.77 103.27,141.77 103.035,142.005 103.035,143.226 C52.2@103.183,143.374 103.266,143.457 103.376,143.457 104.394,144.474 C55.2@104.394,144.585 ; v1@104.961,144.585 C55.2@104.394,144.585 ; C59.2@105.088,147.19 105.2,147.19 v1(105.85,147.839) ; C45.2@99.863,144.898 100.77,144.898 C46.2@100.829,144.839 100.882,144.786 100.882,144.287 C57.2@100.965,144.204 101.06,144.109 102.135,144.109 ; 101.293,143.486 101.293,143.627 101.443,143.777 v1(101.802,143.777) 102.135,144.109
  other v1: 124.519,84.768 122.868,87.689 124.138,91.245 122.487,96.198 130.615,98.484 124.265,99.754 122.487,100.135 129.218,101.024 109.152,101.532 111.057,102.929 124.519,103.437 122.614,103.818 126.17,104.199 109.152,104.834 111.184,106.485 122.995,107.247 127.694,108.39 111.946,109.914 114.74,110.041 120.201,110.168 129.472,110.295 122.868,110.676 127.186,110.93 124.265,112.2 131.504,112.2 125.916,112.835 117.407,112.962 130.869,114.359 133.536,114.359 115.285,114.994 135.949,116.772 132.266,117.915 137.854,118.931 112.962,119.312 136.457,120.074 139.759,120.836 110.041,122.233 139.124,122.614 137.854,123.63 107.904,124.287 139.886,124.519 106.358,125.916 139.886,126.424 104.961,127.313 140.013,128.456 140.013,130.488 139.886,132.393 139.886,134.171 104.128,135.187 103.691,136.457 140.013,136.457 139.886,138.362 105.068,139.781 139.886,140.14 139.886,141.664 96.213,142.949 98.687,142.996 140.013,143.315 96.273,143.784 97.811,144.572 104.976,144.585 139.886,144.839 97.774,146.184 139.886,146.236 96.226,146.955 139.886,147.379 140.013,148.776 96.273,149.384 138.87,150.808 140.394,151.443 136.076,153.856 137.092,154.872 133.79,156.142 134.679,157.158 131.123,158.682 132.647,159.19 127.948,161.73 130.361,161.73 101.68,161.857 126.424,163.254 128.71,163.254 102.421,164.905 125.408,165.032 113.614,165.413 123.884,165.667 127.313,165.667 125.281,166.175 123.757,167.699 125.281,167.699 109.533,168.461 127.059,168.461 107.12,169.477 124.138,169.604 112.708,169.985 111.311,170.493 122.995,170.493 125.789,170.493 124.392,171.636 113.597,172.017 114.994,172.017 116.899,172.017 118.423,172.017 121.725,172.017
HREF: P1.9 U1.A11 | length 27
  Top Layer w0.1: U1.A11@103.024,150.585 103.564,151.125 v1(103.564,151.443) ; v1(110.581,165.921) P1.9@110.581,166.951
  Bottom Layer w0.1: v1(103.564,151.443) 103.564,156.777 105.432,158.645 105.432,158.745 105.342,158.836 105.342,158.936 105.525,159.119 105.625,159.119 105.715,159.028 105.815,159.028 106.026,159.239 106.026,159.339 105.795,159.57 105.795,159.67 105.978,159.853 106.078,159.853 106.309,159.622 106.409,159.622 106.592,159.805 106.592,159.905 106.311,160.186 106.311,160.286 106.494,160.469 106.594,160.469 106.875,160.188 106.975,160.188 107.158,160.371 107.158,160.471 106.877,160.752 106.877,160.852 107.059,161.034 107.159,161.034 107.44,160.753 107.54,160.753 107.723,160.936 107.723,161.036 107.442,161.317 107.442,161.417 107.625,161.6 107.725,161.6 108.006,161.319 108.106,161.319 108.289,161.502 108.289,161.602 108.008,161.883 108.008,161.983 108.191,162.166 108.291,162.166 108.572,161.885 108.672,161.885 108.855,162.068 108.855,162.168 108.574,162.449 108.574,162.549 108.756,162.731 108.856,162.731 109.137,162.45 109.237,162.45 109.42,162.633 109.42,162.733 109.139,163.014 109.139,163.114 109.322,163.297 109.422,163.297 109.703,163.016 109.803,163.016 109.986,163.199 109.986,163.299 109.705,163.58 109.705,163.68 109.888,163.863 109.988,163.863 110.269,163.582 110.369,163.582 110.581,163.794 v1(110.581,165.921)
INITN: pad.55@95.182,118.55 R5.1 U1.T9 U2.8 | length 46.5
  Top Layer w0.254: U2.8@94.288,99.132 94.218,99.062 R5.1@94.218,97.595 94.928,97.595 v1(95.182,97.849) ; v1(96.071,119.439) 99.754,123.122 v1(99.754,133.79) ; U1.T9@101.424,138.585 102.028,137.981 v1(102.04,137.981)
  Bottom Layer w0.254: v1(95.182,97.849) pad.55@95.182,118.55 v1(96.071,119.439) ; v1(99.754,133.79) 102.04,136.076 v1(102.04,137.981)
M_CLK: CARD1.5 U1.C7 | length 24
  Top Layer w0.1: v1(93.586,148.621) 93.603,148.603 99.442,148.603 U1.C7@99.824,148.985
  Top Layer w0.254: CARD1.5@85.219,162.67 85.276,162.613 v1(85.276,157.158)
  Bottom Layer w0.254: v1(85.276,157.158) 85.487,157.158 93.586,149.06 v1(93.586,148.621)
M_CMD: CARD1.3 R20.1 U1.B4 | length 24.7
  Top Layer w0.254: v1(87.419,154.11) CARD1.3@87.419,162.67 ; R20.1@90.728,147.887 90.728,149.148 v1(91.753,150.173) ; v1(97.087,149.411) 97.087,149.448 U1.B4@97.424,149.785
  Bottom Layer w0.254: v1(87.419,154.11) 87.927,154.11 93.107,148.93 93.107,148.422 93.387,148.142 93.784,148.142 93.983,148.341 96.017,148.341 v1(97.087,149.411)
M_D0: CARD1.7 R18.1 U1.B2 | length 21.8
  Top Layer w0.254: v1(83.019,160.333) CARD1.7@83.019,162.67 ; R18.1@90.728,150.935 90.864,151.07 v1(90.864,152.459) ; v1(95.436,149.411) 95.45,149.411 U1.B2@95.824,149.785
  Bottom Layer w0.254: v1(83.019,160.333) 94.42,148.932 94.872,148.932 95.351,149.411 v1(95.436,149.411)
M_D1: CARD1.8 R19.1 U1.B1 | length 25.5
  Top Layer w0.254: CARD1.8@81.919,162.67 81.974,162.615 v1(81.974,161.349) ; R19.1@90.728,153.602 91.363,153.602 94.565,150.4 94.565,150.395 94.834,150.126 94.839,150.126 94.991,149.974 U1.B1@94.991,149.752 ; v1(94.674,149.411) 94.674,149.435 U1.B1@94.991,149.752 ; U1.B1@95.024,149.785 U1.B1@94.991,149.752
  Bottom Layer w0.254: v1(81.974,161.349) 82.736,161.349 v1(94.674,149.411)
M_D2: CARD1.1 R16.1 U1.B6 | length 32.2
  Top Layer w0.1: v1(89.975,149.792) 90.123,149.644 90.123,142.849 R16.1@90.724,142.247
  Top Layer w0.254: CARD1.1@89.619,162.67 89.904,162.385 89.904,149.863 v1(89.975,149.792) ; v1(98.611,149.411) 98.65,149.411 U1.B6@99.024,149.785
  Bottom Layer w0.254: v1(89.975,149.792) 90.229,149.792 91.147,148.874 91.147,148.831 91.427,148.551 91.824,148.551 91.838,148.564 91.963,148.564 92.599,147.928 92.599,147.434 96.634,147.434 v1(98.611,149.411)
M_D3: CARD1.2 R17.1 U1.B5 | length 27.5
  Top Layer w0.254: v1(88.451,152.205) 88.451,162.602 CARD1.2@88.519,162.67 ; R17.1@90.728,144.966 91.41,145.648 91.41,148.814 v1(91.626,149.03) ; v1@97.85,149.411 U1.B5@98.224,149.785
  Bottom Layer w0.254: v1(88.451,152.205) v1(91.626,149.03) 91.998,149.03 93.241,147.788 96.487,147.788 97.849,149.149 v1(97.849,149.411)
